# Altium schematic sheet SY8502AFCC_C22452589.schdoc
size 127 x 101 mm
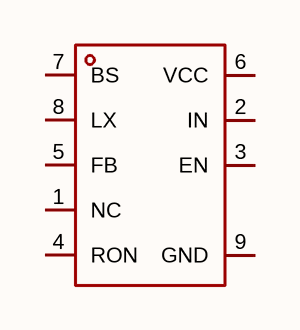
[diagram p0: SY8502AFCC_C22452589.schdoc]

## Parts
U?  sy8502afcc_c22452589  [ESOP-8_L4.9-W3.9-P1.27-LS6.0-BL-EP-1]  (value not drawn)

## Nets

Not connected (* = marked no-connect by the designer): U? 1(NC) 2(IN) 3(EN) 4(RON) 5(FB) 6(VCC) 7(BS) 8(LX) 9(GND)

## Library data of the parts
U? = sy8502afcc_c22452589: 功能类型:降压型;工作电压:7V~85V;输出电压:-;输出电流:1.2A;输出类型:可调;; Manufacturer: Silergy(矽力杰); AddInBom: yes; ModelId: 1edf17d9e1eb44b9aabe355eb95382d1; ModelTransform: 192.913,236.22,0,0,0,0,0,0,0; Function: 降压型; Voltage - Supply: 7V~85V; Output Current: 1.2A; Frequency - Switching: 340kHz；200kHz~500kHz; Synchronous Rectifier: 是; Number of Outputs: 1; Topology: 降压式; Switch tube (built-in/external): 内置; Output Type: 可调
